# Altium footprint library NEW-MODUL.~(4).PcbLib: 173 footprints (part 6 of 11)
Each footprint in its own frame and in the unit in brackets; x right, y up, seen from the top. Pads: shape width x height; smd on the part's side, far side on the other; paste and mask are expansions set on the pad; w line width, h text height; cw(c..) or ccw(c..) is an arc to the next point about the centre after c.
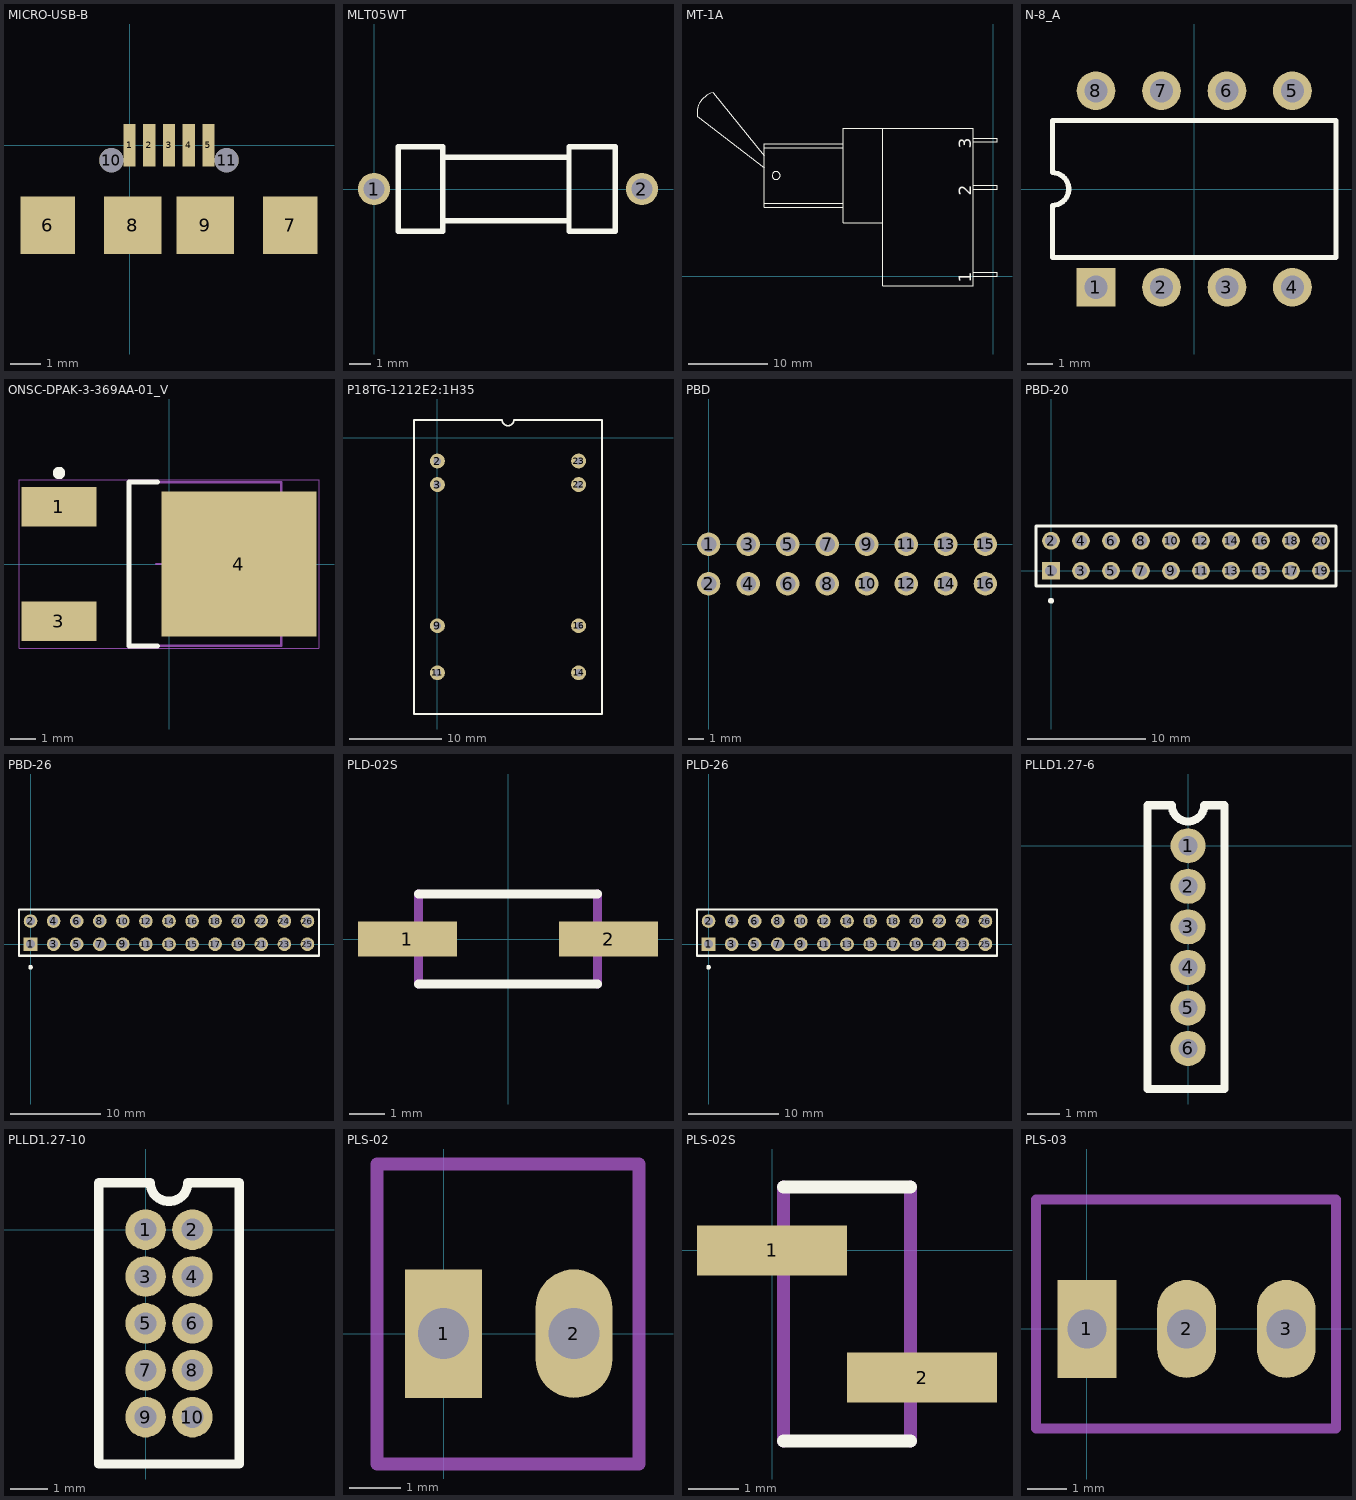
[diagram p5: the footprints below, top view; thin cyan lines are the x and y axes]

## MICRO-USB-B [mm]
pads (11):
  rect 0.4x1.4 smd: 1(0,0) 2(0.65,0) 3(1.3,0) 4(1.95,0) 5(2.6,0)
  rect 1.8x1.9 smd: 6(-2.7,-2.65) 7(5.3,-2.65)
  rect 1.9x1.9 smd: 8(0.1,-2.65) 9(2.5,-2.65)
  round 0.8 hole 0.8 unplated: 10(-0.6,-0.5) 11(3.2,-0.5)
3D body "User Library-Micro USB.step": height 2.74, standoff -0.2, extent -2.72,-5.32 5.26,0.11

## MLT05WT [mil]
pads (2):
  round 60 hole 39.37 unplated: 1(0,0) 2(500,0)
Top Overlay:
  lines w10: 128,-59 128,-79 45,-79 45,79 128,79 128,59 ; 128,-59 128,59 ; 128,-59 364,-59 ; 128,59 364,59 ; 364,-59 364,-29.5 364,29.5 364,59 ; 364,-59 364,-79 450,-79 450,79 364,79 364,59
3D body "User Library-User Library-Half_watt_resistor_500spacing.step": height 153.14, standoff -100.69, extent -14.76,-73.81 514.77,73.82

## MT-1A [mm]
Top Overlay:
  circle w0.025: c-27.5,12.77 r0.5
  lines w0.025: -37.501,20.274 cw(c-34.85,20.67) -35.498,23.27 ; -37.5,20.27 -29,13.77 ; -35.5,23.27 -29,15.27 ; -29,9.27 -19,9.27 ; -29,16.27 -19,16.27 ; -14,18.77 -14,6.77 -19,6.77 -19,18.77 -14,18.77 ; -14,18.77 -14,-1.23 -2.5,-1.23 -2.5,18.77 -14,18.77 ; -29,8.77 -29,16.77 -19,16.77 -19,8.77 -29,8.77 ; -2.5,0.02 -2.5,0.52 0.5,0.52 0.5,0.02 -2.5,0.02 ; -2.5,11.02 -2.5,11.52 0.5,11.52 0.5,11.02 -2.5,11.02 ; -2.5,17.02 -2.5,17.52 0.5,17.52 0.5,17.02 -2.5,17.02
  text "1" at -2.785,-0.81 h1.59
  text "2" at -2.785,10.19 h1.59
  text "3" at -2.785,16.19 h1.59

## N-8_A [mm] "DIP; 8 Leads; Row Spacing 7.62 mm; Pitch 2.54 mm"
height 5.33
pads (8):
  rect 1.5x1.5 hole 0.9: 1(-3.81,-3.81)
  round 1.5 hole 0.9: 2(-1.27,-3.81) 3(1.27,-3.81) 4(3.81,-3.81) 5(3.81,3.81) 6(1.27,3.81) 7(-1.27,3.81) 8(-3.81,3.81)
Top Overlay:
  lines w0.2: -5.5,-2.65 5.5,-2.65 5.5,2.65 -5.5,2.65 -5.5,0.635 cw(c-5.5,0) -5.5,-0.635 -5.5,-2.65
3D body "User Library-DIP8test.STEP": height 4.57, standoff -3.81, extent -4.955,-4.01 4.955,3.81

## ONSC-DPAK-3-369AA-01_V [mm] "DPAK, 3-Leads, Body 6.54x6.095mm, Pitch 2.29mm"
height 2.47
pads (3):
  rect 3x1.6 smd: 1(-4.4,2.29) 3(-4.4,-2.29)
  rect 6.2x5.8 smd: 4(2.8,0)
Top Overlay:
  circle w0.25: c-4.4,3.64 r0.125
  lines w0.2: -0.453,-3.27 -1.6,-3.27 -1.6,3.27 -0.453,3.27
Mechanical 13:
  lines w0.1: -1.6,-3.27 4.495,-3.27 4.495,3.27 -1.6,3.27 -1.6,-3.27
Mechanical 15:
  lines w0.05: 5.99,-3.37 -6,-3.37 -6,3.37 5.99,3.37 ; 6,-3.37 6,3.37
  lines w0.1: -0.5,0 0.5,0 ; 0,-0.5 0,0.5
3D body "User Library-DPAK_TO-252AA.step": height 2.37, standoff -0.03, extent -4.828,-3.367 5.272,3.367

## P18TG-1212E2:1H35 [mm]
pads (8):
  round 1.6 / inner oval 1.8x1.6 / far side round 1.6 hole 0.8: 2(0,-2.54) 3(0,-5.08) 9(0,-20.32) 11(0,-25.4) 14(15.24,-25.4) 16(15.24,-20.32) 22(15.24,-5.08) 23(15.24,-2.54)
Top Overlay:
  lines w0.2: -2.54,-29.845 -2.54,1.905 6.985,1.905 ccw(c7.62,1.905) 8.255,1.905 17.78,1.905 17.78,-29.845 -2.54,-29.845
3D body "User Library-TracoPSU-Ten5-2423.step": height 10.06, standoff -2, extent -2.4,-30 17.6,2

## PBD [mm]
pads (16):
  round 1.5 hole 1: 1(0,0) 2(0,-2.54) 3(2.54,0) 4(2.54,-2.54) 5(5.08,0) 6(5.08,-2.54) 7(7.62,0) 8(7.62,-2.54) 9(10.16,0) 10(10.16,-2.54) 11(12.7,0) 12(12.7,-2.54) 13(15.24,0) 14(15.24,-2.54) 15(17.78,0) 16(17.78,-2.54)
3D body "User Library-PBD2_54-8.STEP": height 8, standoff -3.5, extent -1.532,-3.782 19.288,1.218

## PBD-20 [mm] "Connector; IDC, Low Profile Male Header, Thru-Hole; 10 Position; Vertical; Pitch 2.54 mm"
height 9.45
pads (20):
  rect 1.5x1.5 hole 1 paste-2539.97 mask+0.102: 1(0,0)
  round 1.5 hole 1 paste-2539.97 mask+0.102: 2(0,2.54) 3(2.54,0) 4(2.54,2.54) 5(5.08,0) 6(5.08,2.54) 7(7.62,0) 8(7.62,2.54) 9(10.16,0) 10(10.16,2.54) 11(12.7,0) 12(12.7,2.54) 13(15.24,0) 14(15.24,2.54) 15(17.78,0) 16(17.78,2.54) 17(20.32,0) 18(20.32,2.54) 19(22.86,0) 20(22.86,2.54)
Top Overlay:
  circle w0.25: c0,-2.54 r0.125
  lines w0.254: -1.27,-1.27 -1.27,3.81 24.13,3.81 24.13,-1.27 -1.27,-1.27
3D body "User Library-PBD2_54-10.step": height 8.4, standoff -2.7, extent -1.27,-1.27 11.43,3.81
3D body "User Library-PBD2_54-10.step": height 8.4, standoff -2.7, extent 11.43,-1.27 24.13,3.81

## PBD-26 [mm] "Connector; IDC, Low Profile Male Header, Thru-Hole; 10 Position; Vertical; Pitch 2.54 mm"
height 9.45
pads (26):
  rect 1.5x1.5 hole 1 paste-2539.97 mask+0.102: 1(0,0)
  round 1.5 hole 1 paste-2539.97 mask+0.102: 2(0,2.54) 3(2.54,0) 4(2.54,2.54) 5(5.08,0) 6(5.08,2.54) 7(7.62,0) 8(7.62,2.54) 9(10.16,0) 10(10.16,2.54) 11(12.7,0) 12(12.7,2.54) 13(15.24,0) 14(15.24,2.54) 15(17.78,0) 16(17.78,2.54) 17(20.32,0) 18(20.32,2.54) 19(22.86,0) 20(22.86,2.54) 21(25.4,0) 22(25.4,2.54) 23(27.94,0) 24(27.94,2.54) 25(30.48,0) 26(30.48,2.54)
Top Overlay:
  circle w0.25: c0,-2.54 r0.125
  lines w0.254: -1.27,-1.27 -1.27,3.81 31.75,3.81 31.75,-1.27 -1.27,-1.27
3D body "User Library-PBD2_54-10.step": height 8.4, standoff -2.7, extent -1.27,-1.27 11.43,3.81
3D body "User Library-PBD2_54-10.step": height 8.4, standoff -2.7, extent 11.43,-1.27 24.13,3.81
3D body "User Library-PBD2_54-10.step": height 8.4, standoff -2.7, extent 19.05,-1.27 31.75,3.81

## PLD-02S [mm]
pads (2):
  rect 2.8x1 smd: 1(-2.85,0) 2(2.85,0)
Top Overlay:
  lines w0.254: -2.54,-1.27 2.54,-1.27 ; -2.54,1.27 2.54,1.27
Mechanical 1:
  lines w0.254: -2.54,-1.27 -2.54,1.27 ; 2.54,-1.27 2.54,1.27

## PLD-26 [mm] "Connector; IDC, Low Profile Male Header, Thru-Hole; 26 Position; Vertical; Pitch 2.54 mm"
height 9.45
pads (26):
  rect 1.5x1.5 hole 1 paste-2539.97 mask+0.102: 1(0,0)
  round 1.5 hole 1 paste-2539.97 mask+0.102: 2(0,2.54) 3(2.54,0) 4(2.54,2.54) 5(5.08,0) 6(5.08,2.54) 7(7.62,0) 8(7.62,2.54) 9(10.16,0) 10(10.16,2.54) 11(12.7,0) 12(12.7,2.54) 13(15.24,0) 14(15.24,2.54) 15(17.78,0) 16(17.78,2.54) 17(20.32,0) 18(20.32,2.54) 19(22.86,0) 20(22.86,2.54) 21(25.4,0) 22(25.4,2.54) 23(27.94,0) 24(27.94,2.54) 25(30.48,0) 26(30.48,2.54)
Top Overlay:
  circle w0.25: c0,-2.54 r0.125
  lines w0.254: -1.27,-1.27 -1.27,3.81 31.75,3.81 31.75,-1.27 -1.27,-1.27
3D body "User Library-PLS-1.step": height 8.44, standoff -3, extent 3.81,1.27 6.35,3.81
3D body "User Library-PLS-1.step": height 8.44, standoff -3, extent 6.35,1.27 8.89,3.81
3D body "User Library-PLS-1.step": height 8.44, standoff -3, extent 8.89,1.27 11.43,3.81
3D body "User Library-PLS-1.step": height 8.44, standoff -3, extent -1.27,-1.27 1.27,1.27
3D body "User Library-PLS-1.step": height 8.44, standoff -3, extent 1.27,-1.27 3.81,1.27
3D body "User Library-PLS-1.step": height 8.44, standoff -3, extent 3.81,-1.27 6.35,1.27
3D body "User Library-PLS-1.step": height 8.44, standoff -3, extent 6.35,-1.27 8.89,1.27
3D body "User Library-PLS-1.step": height 8.44, standoff -3, extent 8.89,-1.27 11.43,1.27
3D body "User Library-PLS-1.step": height 8.44, standoff -3, extent 11.43,1.27 13.97,3.81
3D body "User Library-PLS-1.step": height 8.44, standoff -3, extent 11.43,-1.27 13.97,1.27
3D body "User Library-PLS-1.step": height 8.44, standoff -3, extent 13.97,1.27 16.51,3.81
3D body "User Library-PLS-1.step": height 8.44, standoff -3, extent 13.97,-1.27 16.51,1.27
3D body "User Library-PLS-1.step": height 8.44, standoff -3, extent 16.51,1.27 19.05,3.81
3D body "User Library-PLS-1.step": height 8.44, standoff -3, extent 16.51,-1.27 19.05,1.27
3D body "User Library-PLS-1.step": height 8.44, standoff -3, extent 19.05,1.27 21.59,3.81
3D body "User Library-PLS-1.step": height 8.44, standoff -3, extent 19.05,-1.27 21.59,1.27
3D body "User Library-PLS-1.step": height 8.44, standoff -3, extent 21.59,1.27 24.13,3.81
3D body "User Library-PLS-1.step": height 8.44, standoff -3, extent 21.59,-1.27 24.13,1.27
3D body "User Library-PLS-1.step": height 8.44, standoff -3, extent 24.13,1.27 26.67,3.81
3D body "User Library-PLS-1.step": height 8.44, standoff -3, extent 24.13,-1.27 26.67,1.27
3D body "User Library-PLS-1.step": height 8.44, standoff -3, extent 26.67,1.27 29.21,3.81
3D body "User Library-PLS-1.step": height 8.44, standoff -3, extent 26.67,-1.27 29.21,1.27
3D body "User Library-PLS-1.step": height 8.44, standoff -3, extent 29.21,1.27 31.75,3.81
3D body "User Library-PLS-1.step": height 8.44, standoff -3, extent 29.21,-1.27 31.75,1.27
3D body "User Library-PLS-1.step": height 8.44, standoff -3, extent 1.27,1.27 3.81,3.81
3D body "User Library-PLS-1.step": height 8.44, standoff -3, extent -1.27,1.27 1.27,3.81

## PLLD1.27-6 [mm]
pads (6):
  round 1.1 hole 0.6: 1(0,0) 2(0,-1.27) 3(0,-2.54) 4(0,-3.81) 5(0,-5.08) 6(0,-6.35)
Top Overlay:
  lines w0.254: -1.27,-7.62 -1.27,1.27 -0.508,1.27 ccw(c0,1.27) 0.508,1.27 1.143,1.27 1.143,-7.62 -1.27,-7.62

## PLLD1.27-10 [mm]
pads (10):
  round 1.1 hole 0.6: 1(0,0) 2(1.27,0) 3(0,-1.27) 4(1.27,-1.27) 5(0,-2.54) 6(1.27,-2.54) 7(0,-3.81) 8(1.27,-3.81) 9(0,-5.08) 10(1.27,-5.08)
Top Overlay:
  lines w0.254: -1.27,-6.35 2.54,-6.35 2.54,1.27 1.143,1.27 cw(c0.635,1.27) 0.127,1.27 -1.27,1.27 -1.27,-6.35

## PLS-02 [mm]
pads (2):
  rect 1.5x2.5 hole 1: 1(0,0)
  oval 1.5x2.5 hole 1: 2(2.54,0)
Mechanical 15:
  lines w0.254: -1.3,-2.54 -1.3,3.302 3.81,3.302 3.81,-2.54 -1.3,-2.54
3D body "User Library-CI31_2.step": height 11.51, standoff -3.29, extent -1.27,-2.521 3.81,3.279

## PLS-02S [mm]
pads (2):
  rect 3x1 smd: 1(0,0) 2(3,-2.54)
Top Overlay:
  lines w0.254: 0.23,-3.81 2.77,-3.81 ; 0.23,1.27 2.77,1.27
Mechanical 1:
  lines w0.254: 0.23,-3.81 0.23,1.27 ; 2.77,-3.81 2.77,1.27
3D body "pin_header_a-sl254-eg-g02mp1.stp": height 9.86, standoff 0.02, extent -1,-3.79 4,1.29

## PLS-03 [mm]
pads (3):
  rect 1.5x2.5 hole 1: 1(0,0)
  oval 1.5x2.5 hole 1: 2(2.54,0) 3(5.08,0)
Mechanical 15:
  lines w0.254: -1.3,-2.54 6.35,-2.54 6.35,3.302 -1.3,3.302 -1.3,-2.54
